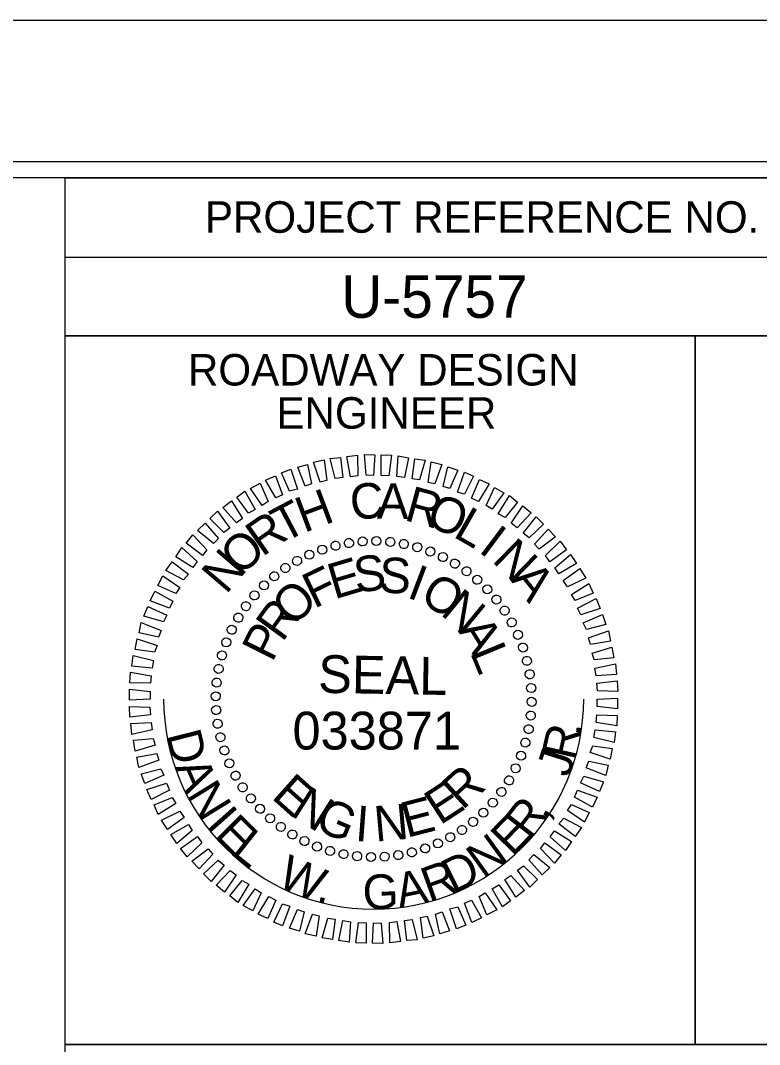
# Model space of a CAD drawing. Extents: x 957297 to 961629, y 830661 to 840840.
# Drawn here: x 960170.6 to 960288, y 835525.5 to 835688 of the extents above; entities that cross this region are included whole.
import ezdxf

# ---------------------------------------------------------------- set-up
doc = ezdxf.new("R2010")
doc.units = 0
for name, color, linetype in [('Scratch_Level_0', 7, 'Continuous'), ('Sheet Data Field CELL', 7, 'Continuous'), ('Sheet Plot Border Inside CELL', 7, 'Continuous'), ('Sheet Plot Border Outside CELL', 7, 'Continuous'), ('Sheet Professional Seal CELL', 7, 'Continuous'), ('Sheet Profile Grid Minor CELL', 7, 'Continuous'), ('Sheet Sticker Exception Certification CELL', 7, 'Continuous'), ('Sheet Typical CELL', 7, 'Continuous')]:
    doc.layers.add(name, color=color, linetype=linetype)

msp = doc.modelspace()

# ---------------------------------------------------------------- linework, layer by layer
at = {"layer": 'Scratch_Level_0'}
msp.add_arc((960226.74, 835580.31), 33.36, 180, 360, dxfattribs=at)
at = {"layer": 'Sheet Plot Border Inside CELL'}
msp.add_lwpolyline([(960390.3, 835665.58), (958723.8, 835665.58), (958723.8, 834610.48), (960390.3, 834610.48)], close=True, dxfattribs=at)
at = {"layer": 'Sheet Plot Border Outside CELL'}
msp.add_lwpolyline([(960394.8, 835688.03), (958710.8, 835688.03), (958710.8, 834588.03), (960394.8, 834588.03)], close=True, dxfattribs=at)
at = {"layer": 'Sheet Professional Seal CELL'}
for p, q in [((960220.64, 835604.66), (960220.64, 835604.66)), ((960222.84, 835605.06), (960222.84, 835605.06)), ((960224.99, 835605.36), (960224.99, 835605.36)), ((960227.19, 835605.41), (960227.19, 835605.41)), ((960229.39, 835605.26), (960229.39, 835605.26)), ((960231.54, 835604.91), (960231.54, 835604.91)), ((960233.64, 835604.46), (960233.64, 835604.46)), ((960216.54, 835603.26), (960216.54, 835603.26)), ((960218.54, 835604.06), (960218.54, 835604.06)), ((960235.74, 835603.76), (960235.74, 835603.76)), ((960237.74, 835602.86), (960237.74, 835602.86)), ((960212.69, 835601.11), (960212.69, 835601.11)), ((960214.59, 835602.26), (960214.59, 835602.26)), ((960239.69, 835601.86), (960239.69, 835601.86)), ((960210.94, 835599.86), (960210.94, 835599.86)), ((960241.49, 835600.61), (960241.49, 835600.61)), ((960209.29, 835598.36), (960209.29, 835598.36)), ((960243.24, 835599.26), (960243.24, 835599.26)), ((960244.79, 835597.76), (960244.79, 835597.76)), ((960207.79, 835596.81), (960207.79, 835596.81)), ((960246.29, 835596.11), (960246.29, 835596.11)), ((960206.44, 835595.06), (960206.44, 835595.06)), ((960205.19, 835593.26), (960205.19, 835593.26)), ((960247.54, 835594.36), (960247.54, 835594.36)), ((960204.19, 835591.31), (960204.19, 835591.31)), ((960248.69, 835592.46), (960248.69, 835592.46)), ((960249.69, 835590.51), (960249.69, 835590.51)), ((960203.29, 835589.31), (960203.29, 835589.31)), ((960250.49, 835588.51), (960250.49, 835588.51)), ((960202.59, 835587.21), (960202.59, 835587.21)), ((960251.09, 835586.41), (960251.09, 835586.41)), ((960202.14, 835585.11), (960202.14, 835585.11)), ((960251.49, 835584.21), (960251.49, 835584.21)), ((960201.79, 835582.96), (960201.79, 835582.96)), ((960251.79, 835582.06), (960251.79, 835582.06)), ((960201.64, 835580.76), (960201.64, 835580.76)), ((960226.74, 835580.31), (960226.74, 835580.31)), ((960251.84, 835579.86), (960251.84, 835579.86)), ((960201.69, 835578.56), (960201.69, 835578.56)), ((960251.69, 835577.66), (960251.69, 835577.66)), ((960201.99, 835576.41), (960201.99, 835576.41)), ((960251.34, 835575.51), (960251.34, 835575.51)), ((960202.39, 835574.21), (960202.39, 835574.21)), ((960250.89, 835573.41), (960250.89, 835573.41)), ((960202.99, 835572.11), (960202.99, 835572.11)), ((960203.79, 835570.11), (960203.79, 835570.11)), ((960250.19, 835571.31), (960250.19, 835571.31)), ((960249.29, 835569.31), (960249.29, 835569.31)), ((960204.79, 835568.16), (960204.79, 835568.16)), ((960248.29, 835567.36), (960248.29, 835567.36)), ((960205.94, 835566.26), (960205.94, 835566.26)), ((960247.04, 835565.56), (960247.04, 835565.56)), ((960207.19, 835564.51), (960207.19, 835564.51)), ((960245.69, 835563.81), (960245.69, 835563.81)), ((960208.69, 835562.86), (960208.69, 835562.86)), ((960244.19, 835562.26), (960244.19, 835562.26)), ((960210.24, 835561.36), (960210.24, 835561.36)), ((960242.54, 835560.76), (960242.54, 835560.76)), ((960211.99, 835560.01), (960211.99, 835560.01)), ((960213.79, 835558.76), (960213.79, 835558.76)), ((960240.79, 835559.51), (960240.79, 835559.51)), ((960215.74, 835557.76), (960215.74, 835557.76)), ((960236.94, 835557.36), (960236.94, 835557.36)), ((960238.89, 835558.36), (960238.89, 835558.36)), ((960217.74, 835556.86), (960217.74, 835556.86)), ((960219.84, 835556.16), (960219.84, 835556.16)), ((960221.94, 835555.71), (960221.94, 835555.71)), ((960230.64, 835555.56), (960230.64, 835555.56)), ((960232.84, 835555.96), (960232.84, 835555.96)), ((960234.94, 835556.56), (960234.94, 835556.56)), ((960224.09, 835555.36), (960224.09, 835555.36)), ((960226.29, 835555.21), (960226.29, 835555.21)), ((960228.49, 835555.26), (960228.49, 835555.26))]:
    msp.add_line(p, q, dxfattribs=at)
for points in [[(960223.04, 835615.61), (960222.49, 835618.81), (960224.19, 835619.01), (960224.24, 835615.76)], [(960225.54, 835615.86), (960225.29, 835619.11), (960226.94, 835619.06), (960226.74, 835615.81)], [(960227.94, 835615.81), (960227.94, 835619.06), (960229.59, 835619.01), (960229.14, 835615.76)], [(960230.44, 835615.66), (960230.64, 835618.91), (960232.29, 835618.61), (960231.64, 835615.46)], [(960215.84, 835614.11), (960214.69, 835617.11), (960216.24, 835617.56), (960216.89, 835614.46)], [(960218.24, 835614.76), (960217.19, 835617.91), (960218.89, 835618.26), (960219.29, 835615.01)], [(960220.64, 835615.31), (960219.84, 835618.51), (960221.49, 835618.66), (960221.84, 835615.46)], [(960232.84, 835615.26), (960233.29, 835618.46), (960234.94, 835618.21), (960234.04, 835615.11)], [(960235.39, 835614.71), (960235.89, 835617.96), (960237.59, 835617.56), (960236.44, 835614.46)], [(960237.79, 835614.06), (960238.54, 835617.16), (960240.09, 835616.66), (960238.84, 835613.71)], [(960211.19, 835612.26), (960209.59, 835615.06), (960211.14, 835615.76), (960212.29, 835612.71)], [(960213.39, 835613.31), (960212.09, 835616.21), (960213.59, 835616.81), (960214.64, 835613.61)], [(960240.04, 835613.16), (960241.19, 835616.31), (960242.59, 835615.71), (960241.19, 835612.81)], [(960209.04, 835611.06), (960207.19, 835613.76), (960208.74, 835614.56), (960209.99, 835611.66)], [(960242.29, 835612.21), (960243.54, 835615.16), (960245.09, 835614.46), (960243.39, 835611.66)], [(960244.59, 835611.06), (960245.94, 835613.91), (960247.44, 835613.06), (960245.54, 835610.46)], [(960206.84, 835609.81), (960204.99, 835612.36), (960206.29, 835613.31), (960207.94, 835610.41)], [(960246.54, 835609.71), (960248.29, 835612.61), (960249.59, 835611.56), (960247.64, 835609.11)], [(960204.94, 835608.31), (960202.79, 835610.71), (960204.14, 835611.76), (960205.89, 835608.96)], [(960248.59, 835608.21), (960250.44, 835610.96), (960251.74, 835609.86), (960249.54, 835607.51)], [(960202.94, 835606.76), (960200.74, 835608.96), (960201.94, 835610.16), (960203.89, 835607.46)], [(960250.49, 835606.66), (960252.54, 835609.26), (960253.74, 835608.06), (960251.44, 835605.91)], [(960201.29, 835605.01), (960198.74, 835607.06), (960199.99, 835608.21), (960202.09, 835605.81)], [(960199.54, 835603.11), (960196.94, 835605.06), (960198.04, 835606.36), (960200.24, 835604.01)], [(960252.29, 835604.91), (960254.44, 835607.26), (960255.64, 835606.06), (960253.04, 835604.11)], [(960198.04, 835601.21), (960195.34, 835602.91), (960196.29, 835604.36), (960198.69, 835602.16)], [(960254.04, 835603.11), (960256.34, 835605.36), (960257.39, 835604.01), (960254.74, 835602.11)], [(960255.54, 835601.16), (960257.99, 835603.26), (960258.94, 835601.81), (960256.14, 835600.21)], [(960196.54, 835599.21), (960193.74, 835600.71), (960194.74, 835602.11), (960197.34, 835600.11)], [(960256.84, 835599.11), (960259.49, 835601.01), (960260.44, 835599.51), (960257.54, 835598.11)], [(960195.34, 835597.06), (960192.49, 835598.31), (960193.24, 835599.86), (960195.94, 835598.01)], [(960258.14, 835596.91), (960260.94, 835598.66), (960261.59, 835597.11), (960258.74, 835595.96)], [(960194.34, 835594.76), (960191.24, 835595.91), (960191.99, 835597.46), (960194.84, 835595.86)], [(960259.14, 835594.76), (960262.09, 835596.26), (960262.74, 835594.66), (960259.64, 835593.66)], [(960193.34, 835592.56), (960190.24, 835593.46), (960190.89, 835595.01), (960193.89, 835593.61)], [(960260.04, 835592.41), (960263.09, 835593.71), (960263.64, 835592.16), (960260.54, 835591.36)], [(960192.59, 835590.16), (960189.49, 835590.81), (960189.84, 835592.46), (960192.99, 835591.21)], [(960260.84, 835590.01), (960264.04, 835591.16), (960264.34, 835589.51), (960261.19, 835588.96)], [(960191.94, 835587.76), (960188.84, 835588.16), (960189.19, 835589.86), (960192.34, 835588.81)], [(960261.44, 835587.61), (960264.59, 835588.56), (960264.89, 835586.86), (960261.74, 835586.56)], [(960191.54, 835585.21), (960188.34, 835585.51), (960188.54, 835587.21), (960191.79, 835586.41)], [(960261.89, 835585.21), (960265.14, 835585.91), (960265.29, 835584.21), (960262.09, 835584.01)], [(960191.29, 835582.81), (960188.04, 835582.91), (960188.14, 835584.56), (960191.39, 835584.01)], [(960262.19, 835582.81), (960265.44, 835583.21), (960265.54, 835581.51), (960262.29, 835581.61)], [(960191.24, 835580.31), (960187.99, 835580.16), (960187.99, 835581.86), (960191.24, 835581.51)], [(960262.24, 835580.31), (960265.49, 835580.46), (960265.49, 835578.76), (960262.24, 835579.11)], [(960191.29, 835577.81), (960188.04, 835577.41), (960187.94, 835579.11), (960191.19, 835579.01)], [(960191.59, 835575.41), (960188.34, 835574.71), (960188.19, 835576.41), (960191.39, 835576.61)], [(960262.19, 835577.81), (960265.44, 835577.71), (960265.34, 835576.06), (960262.09, 835576.61)], [(960261.94, 835575.41), (960265.14, 835575.11), (960264.94, 835573.41), (960261.69, 835574.21)], [(960192.04, 835573.01), (960188.89, 835572.06), (960188.59, 835573.76), (960191.74, 835574.06)], [(960192.64, 835570.61), (960189.44, 835569.46), (960189.14, 835571.11), (960192.29, 835571.66)], [(960261.54, 835572.86), (960264.64, 835572.46), (960264.29, 835570.76), (960261.14, 835571.81)], [(960260.89, 835570.46), (960263.99, 835569.81), (960263.64, 835568.16), (960260.49, 835569.41)], [(960193.44, 835568.21), (960190.39, 835566.91), (960189.84, 835568.46), (960192.94, 835569.26)], [(960194.34, 835565.86), (960191.39, 835564.36), (960190.74, 835565.96), (960193.84, 835566.96)], [(960260.14, 835568.06), (960263.24, 835567.16), (960262.59, 835565.61), (960259.59, 835567.01)], [(960259.14, 835565.86), (960262.24, 835564.71), (960261.49, 835563.16), (960258.64, 835564.76)], [(960195.34, 835563.71), (960192.54, 835561.96), (960191.89, 835563.51), (960194.74, 835564.66)], [(960258.14, 835563.56), (960260.99, 835562.31), (960260.24, 835560.76), (960257.54, 835562.61)], [(960196.64, 835561.51), (960193.99, 835559.61), (960193.04, 835561.11), (960195.94, 835562.51)], [(960197.94, 835559.46), (960195.49, 835557.36), (960194.54, 835558.81), (960197.34, 835560.41)], [(960256.94, 835561.41), (960259.74, 835559.91), (960258.74, 835558.51), (960256.14, 835560.51)], [(960255.44, 835559.41), (960258.14, 835557.71), (960257.19, 835556.26), (960254.79, 835558.46)], [(960199.44, 835557.51), (960197.14, 835555.26), (960196.09, 835556.61), (960198.74, 835558.51)], [(960253.94, 835557.51), (960256.54, 835555.56), (960255.44, 835554.26), (960253.24, 835556.61)], [(960201.19, 835555.71), (960199.04, 835553.36), (960197.84, 835554.56), (960200.44, 835556.51)], [(960252.19, 835555.61), (960254.74, 835553.56), (960253.49, 835552.41), (960251.39, 835554.81)], [(960202.99, 835553.96), (960200.94, 835551.36), (960199.74, 835552.56), (960202.04, 835554.71)], [(960250.54, 835553.86), (960252.74, 835551.66), (960251.54, 835550.46), (960249.59, 835553.16)], [(960204.89, 835552.41), (960203.04, 835549.66), (960201.74, 835550.76), (960203.94, 835553.11)], [(960248.54, 835552.31), (960250.69, 835549.91), (960249.34, 835548.86), (960247.59, 835551.66)], [(960206.94, 835550.91), (960205.19, 835548.01), (960203.89, 835549.06), (960205.84, 835551.51)], [(960246.64, 835550.81), (960248.49, 835548.26), (960247.19, 835547.31), (960245.54, 835550.21)], [(960208.89, 835549.56), (960207.54, 835546.71), (960206.04, 835547.56), (960207.94, 835550.16)], [(960211.19, 835548.41), (960209.94, 835545.46), (960208.39, 835546.16), (960210.09, 835548.96)], [(960244.44, 835549.56), (960246.29, 835546.86), (960244.74, 835546.06), (960243.49, 835548.96)], [(960213.44, 835547.46), (960212.29, 835544.31), (960210.89, 835544.91), (960212.29, 835547.81)], [(960240.09, 835547.31), (960241.39, 835544.41), (960239.89, 835543.81), (960238.84, 835547.01)], [(960242.29, 835548.36), (960243.89, 835545.56), (960242.34, 835544.86), (960241.19, 835547.91)], [(960215.69, 835546.56), (960214.94, 835543.46), (960213.39, 835543.96), (960214.64, 835546.91)], [(960218.09, 835545.91), (960217.59, 835542.66), (960215.89, 835543.06), (960217.04, 835546.16)], [(960235.24, 835545.86), (960236.29, 835542.71), (960234.59, 835542.36), (960234.19, 835545.61)], [(960237.64, 835546.51), (960238.79, 835543.51), (960237.24, 835543.06), (960236.59, 835546.16)], [(960220.64, 835545.36), (960220.19, 835542.16), (960218.54, 835542.41), (960219.44, 835545.51)], [(960223.04, 835544.96), (960222.84, 835541.71), (960221.19, 835542.01), (960221.84, 835545.16)], [(960225.54, 835544.81), (960225.54, 835541.56), (960223.89, 835541.61), (960224.34, 835544.86)], [(960227.94, 835544.76), (960228.19, 835541.51), (960226.54, 835541.56), (960226.74, 835544.81)], [(960230.44, 835545.01), (960230.99, 835541.81), (960229.29, 835541.61), (960229.24, 835544.86)], [(960232.84, 835545.31), (960233.64, 835542.11), (960231.99, 835541.96), (960231.64, 835545.16)]]:
    msp.add_lwpolyline(points, close=True, dxfattribs=at)
for centre, major_axis in [((960222.82, 835605.08), (-0.113, 0.711)), ((960224.99, 835605.33), (-0.05, 0.718)), ((960227.18, 835605.39), (0.013, 0.72)), ((960229.37, 835605.26), (0.075, 0.716)), ((960218.58, 835604.03), (-0.234, 0.681)), ((960220.68, 835604.65), (-0.174, 0.699)), ((960231.53, 835604.93), (0.137, 0.707)), ((960233.66, 835604.42), (0.198, 0.692)), ((960235.73, 835603.73), (0.258, 0.672)), ((960214.58, 835602.25), (-0.349, 0.63)), ((960216.54, 835603.22), (-0.293, 0.658)), ((960237.74, 835602.85), (0.316, 0.647)), ((960239.66, 835601.81), (0.371, 0.617)), ((960212.72, 835601.1), (-0.403, 0.597)), ((960241.49, 835600.6), (0.423, 0.582)), ((960210.96, 835599.8), (-0.453, 0.56)), ((960243.2, 835599.24), (0.472, 0.543)), ((960209.32, 835598.35), (-0.5, 0.518)), ((960244.79, 835597.73), (0.518, 0.5)), ((960207.82, 835596.77), (-0.543, 0.472)), ((960246.23, 835596.1), (0.56, 0.453)), ((960206.45, 835595.05), (-0.582, 0.423)), ((960247.54, 835594.34), (0.597, 0.403)), ((960205.25, 835593.23), (-0.617, 0.371)), ((960248.68, 835592.47), (0.63, 0.349)), ((960204.2, 835591.31), (-0.647, 0.316)), ((960249.66, 835590.51), (0.658, 0.293)), ((960203.33, 835589.3), (-0.672, 0.258)), ((960202.64, 835587.23), (-0.692, 0.198)), ((960250.46, 835588.48), (0.681, 0.234)), ((960251.08, 835586.38), (0.699, 0.174)), ((960202.12, 835585.1), (-0.707, 0.137)), ((960251.52, 835584.24), (0.711, 0.113)), ((960201.8, 835582.93), (-0.716, 0.075)), ((960201.67, 835580.75), (-0.72, 0.013)), ((960251.76, 835582.06), (0.718, 0.05)), ((960251.82, 835579.87), (0.72, -0.013)), ((960201.73, 835578.56), (-0.718, -0.05)), ((960251.69, 835577.69), (0.716, -0.075)), ((960201.97, 835576.39), (-0.711, -0.113)), ((960202.41, 835574.25), (-0.699, -0.174)), ((960251.36, 835575.53), (0.707, -0.137)), ((960250.85, 835573.4), (0.692, -0.198)), ((960203.03, 835572.15), (-0.681, -0.234)), ((960250.16, 835571.32), (0.672, -0.258)), ((960203.83, 835570.11), (-0.658, -0.293)), ((960249.29, 835569.32), (0.647, -0.316)), ((960204.81, 835568.15), (-0.63, -0.349)), ((960205.95, 835566.29), (-0.597, -0.403)), ((960248.24, 835567.4), (0.617, -0.371)), ((960207.25, 835564.53), (-0.56, -0.453)), ((960247.03, 835565.57), (0.582, -0.423)), ((960208.7, 835562.89), (-0.518, -0.5)), ((960245.67, 835563.86), (0.543, -0.472)), ((960210.29, 835561.38), (-0.472, -0.543)), ((960244.17, 835562.27), (0.5, -0.518)), ((960212, 835560.02), (-0.423, -0.582)), ((960240.77, 835559.52), (0.403, -0.597)), ((960242.53, 835560.82), (0.453, -0.56)), ((960213.83, 835558.81), (-0.371, -0.617)), ((960238.9, 835558.38), (0.349, -0.63)), ((960215.75, 835557.77), (-0.316, -0.647)), ((960217.76, 835556.9), (-0.258, -0.672)), ((960234.91, 835556.6), (0.234, -0.681)), ((960236.94, 835557.4), (0.293, -0.658)), ((960219.83, 835556.2), (-0.198, -0.692)), ((960221.96, 835555.69), (-0.137, -0.707)), ((960224.12, 835555.37), (-0.075, -0.716)), ((960226.31, 835555.24), (-0.013, -0.72)), ((960228.49, 835555.29), (0.05, -0.718)), ((960230.67, 835555.54), (0.113, -0.711)), ((960232.81, 835555.98), (0.174, -0.699))]:
    msp.add_ellipse(centre, major_axis=major_axis, ratio=0.999708, dxfattribs=at)
at = {"layer": 'Sheet Sticker Exception Certification CELL'}
for p, q in [((960177.75, 835501.98), (960177.75, 835525.48)), ((960177.75, 835525.48), (960377.79, 835525.48))]:
    msp.add_line(p, q, dxfattribs=at)
at = {"layer": 'Sheet Typical CELL'}
for p, q in [((960177.75, 835650.48), (960377.8, 835650.48)), ((960277.8, 835637.98), (960277.8, 835525.53))]:
    msp.add_line(p, q, dxfattribs=at)
for points in [[(960377.8, 835663.03), (958877.8, 835663.03), (958877.8, 834613.03), (960377.8, 834613.03)], [(960177.75, 835663.03), (960377.8, 835663.03), (960377.8, 835637.98), (960177.75, 835637.98)], [(960177.75, 835637.98), (960277.8, 835637.98), (960277.8, 835525.48), (960177.75, 835525.48)], [(960277.8, 835637.98), (960377.8, 835637.98), (960377.8, 835525.48), (960277.8, 835525.48)]]:
    msp.add_lwpolyline(points, close=True, dxfattribs=at)

# ---------------------------------------------------------------- texts
at = {"layer": 'Sheet Data Field CELL'}
msp.add_text('U-5757', height=6.75, dxfattribs=at).set_placement((960221.59, 835640.83))
at = {"layer": 'Sheet Professional Seal CELL'}
for s, height, rotation, p in [('C', 5.64, 6.2199, (960223.29, 835608.66)), ('A', 5.64, 359.0203, (960227.24, 835608.96)), ('R', 5.64, 344.6211, (960231.44, 835608.76)), ('H', 5.64, 20.6195, (960215.69, 835606.66)), ('O', 5.64, 337.4212, (960234.79, 835608.01)), ('T', 5.64, 27.8198, (960212.44, 835605.01)), ('L', 5.64, 330.2209, (960239.19, 835606.16)), ('R', 5.64, 35.0205, (960209.04, 835602.81)), ('I', 5.64, 323.0201, (960243.24, 835603.76)), ('O', 5.64, 42.2217, (960205.59, 835599.71)), ('N', 5.64, 315.8189, (960245.39, 835602.21)), ('N', 5.64, 49.4235, (960203.29, 835596.81)), ('E', 5.64, 16.6111, (960220.49, 835596.11)), ('S', 5.64, 7.2556, (960223.94, 835597.16)), ('S', 5.64, 357.9004, (960227.54, 835597.21)), ('F', 5.64, 25.967, (960217.29, 835594.61)), ('I', 5.64, 339.1896, (960231.84, 835596.51)), ('A', 5.64, 308.6172, (960248.34, 835599.26)), ('O', 5.64, 329.8335, (960233.84, 835595.81)), ('O', 5.64, 44.6812, (960213.99, 835591.66)), ('N', 5.64, 320.4766, (960237.19, 835593.81)), ('R', 5.64, 54.0396, (960212.24, 835589.21)), ('P', 5.64, 63.3989, (960210.64, 835586.01)), ('A', 5.64, 301.7603, (960240.04, 835591.21)), ('L', 5.64, 292.4008, (960241.99, 835587.76)), ('SEAL', 5.998, 359, (960217.89, 835581.31)), ('E', 5.64, 318.2769, (960210.34, 835564.66)), ('R', 5.64, 42.4814, (960240.84, 835562.56)), ('E', 5.64, 33.1241, (960237.29, 835560.21)), ('N', 5.64, 327.634, (960213.34, 835561.96)), ('G', 5.64, 336.9902, (960217.14, 835559.71)), ('N', 5.64, 5.0564, (960227.04, 835557.66)), ('E', 5.64, 14.4118, (960231.99, 835558.26)), ('I', 5.64, 355.7012, (960223.69, 835557.81))]:
    msp.add_text(s, height=height, rotation=rotation, dxfattribs=at).set_placement(p)
at = {"layer": 'Sheet Profile Grid Minor CELL'}
for s, height, rotation, p in [('033871', 5.998, 360, (960213.85, 835572.3)), ('D', 5.5, 284.2682, (960193.75, 835574.67)), ('R', 5.5, 77.3541, (960258.72, 835570.41)), ('.', 5.5, 84.2805, (960259.68, 835574.34)), ('J', 5.5, 72.4855, (960257.76, 835567.73)), ('A', 5.5, 293.4128, (960195.07, 835569.5)), ('N', 5.5, 301.5986, (960196.93, 835565.1)), ('R', 5.5, 52.3788, (960251.55, 835557.84)), ('I', 5.5, 311.5304, (960200, 835560.18)), ('E', 5.5, 315.0508, (960201.29, 835558.58)), ('E', 5.5, 45.7958, (960248.8, 835555.14)), (',', 5.5, 59.3052, (960254.07, 835560.99)), ('L', 5.5, 321.6338, (960203.95, 835555.81)), ('N', 5.5, 35.8641, (960244.13, 835551.71)), ('W', 5.5, 336.8891, (960211.2, 835550.67)), ('D', 5.5, 26.7195, (960239.37, 835549.31)), ('R', 5.5, 19.793, (960235.54, 835548.02)), ('G', 5.5, 1.6755, (960225.06, 835546.89)), ('A', 5.5, 11.6072, (960230.85, 835547.1)), ('.', 5.5, 348.4952, (960217.48, 835548.15))]:
    msp.add_text(s, height=height, rotation=rotation, dxfattribs=at).set_placement(p)
at = {"layer": 'Sheet Typical CELL'}
for s, height, p in [('PROJECT REFERENCE NO.', 5.0001, (960199.95, 835654.33)), ('ROADWAY DESIGN', 5.0001, (960197.25, 835630.08)), ('ENGINEER', 5, (960211.3, 835623.23))]:
    msp.add_text(s, height=height, dxfattribs=at).set_placement(p)

doc.saveas('drawing.dxf')
